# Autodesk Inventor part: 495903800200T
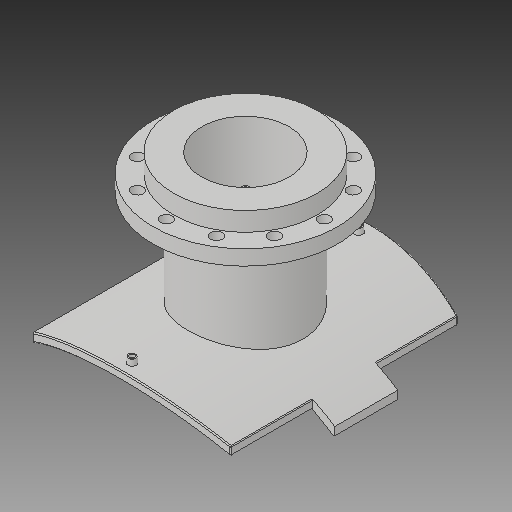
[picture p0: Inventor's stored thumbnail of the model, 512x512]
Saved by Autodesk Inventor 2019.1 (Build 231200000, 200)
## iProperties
Created: 2017-10
Part Number: 495903800200T
Material: Generic
Description: PLASSON FLANGED BRANCH SADDLE 800X200
Document SubType Name: Modeling
Designer: KIM
Mass: 2339.99 g
Surface Area: 3251.55 cm^2
Volume: 2339.99 cm^3
Density: 1 g/cm^3
Appearance: Default
Author: KIM
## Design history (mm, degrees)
derived "495904_495903.ipt"
feature "Solid1::495904_495903.ipt"
feature "Solid2::495904_495903.ipt"
tag "TaggingFeature1"
body "Solid1"
other parameters: "d1" = 15, "d2" = 369, "d4" = 0, "d6" = 117.5, "d7" = 0, "d12" = 425.6, "d13" = 14, "d14" = 211.5, "d16" = 5 deg, "d18" = 4, "d19" = 14, "d20" = 0, "d21" = 3, "d22" = 0, "d23" = 665, "d36" = 211.5, "d38" = 0, "d39" = 2, "d41" = 163, "d42" = 268, "d43" = 344, "d46" = 214.4, "d47" = 16, "d48" = 10.4, "d49" = 175, "d51" = 816, "d53" = 0, "d54" = 22, "d55" = 147.5, "d57" = 0, "d59" = 360 deg, "d61" = 28, "d63" = 0, "d67" = 15, "d68" = 125, "d70" = 0, "d71" = 2, "d_1" = 268, "x_" = 15, "D_" = 16, "DN_" = 163, "D_1" = 344, "t_" = 28, "s_" = 22, "Dp_" = 295
